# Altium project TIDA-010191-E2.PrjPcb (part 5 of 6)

## Sheet TIDA-010191-E2_Power-Supply_2.SchDoc
size 558 x 431 mm; Date: Not shown in title block; ApprovedBy: Not shown in title block; CheckedBy: Not shown in title block; Author: Not shown in title block; CompanyName: Not shown in title block; Engineer: Not shown in title block; Organization: Not shown in title block; Address1: Not shown in title block; Address2: Not shown in title block; Address3: Not shown in title block; Address4: Not shown in title block; DocumentNumber: 7; Revision: Use project parameter SCH_Rev; SheetNumber: 7; SheetTotal: 9; PageSetup: Record=PageOptions¦CenterHorizontal=True¦CenterVertical=True¦PrintScale=1.00¦XCorrection=1.00¦YCorrection=1.00¦PrintKind=0¦BorderSize=5000000¦LeftOffset=0¦BottomOffset=0¦Orientation=2¦PaperLength=1000¦PaperWidth=1000¦Scale=100¦PaperSource=15¦PrintQuality=600¦MediaType=1¦DitherType=10¦PaperKind=Letter¦PrintScaleMode=1
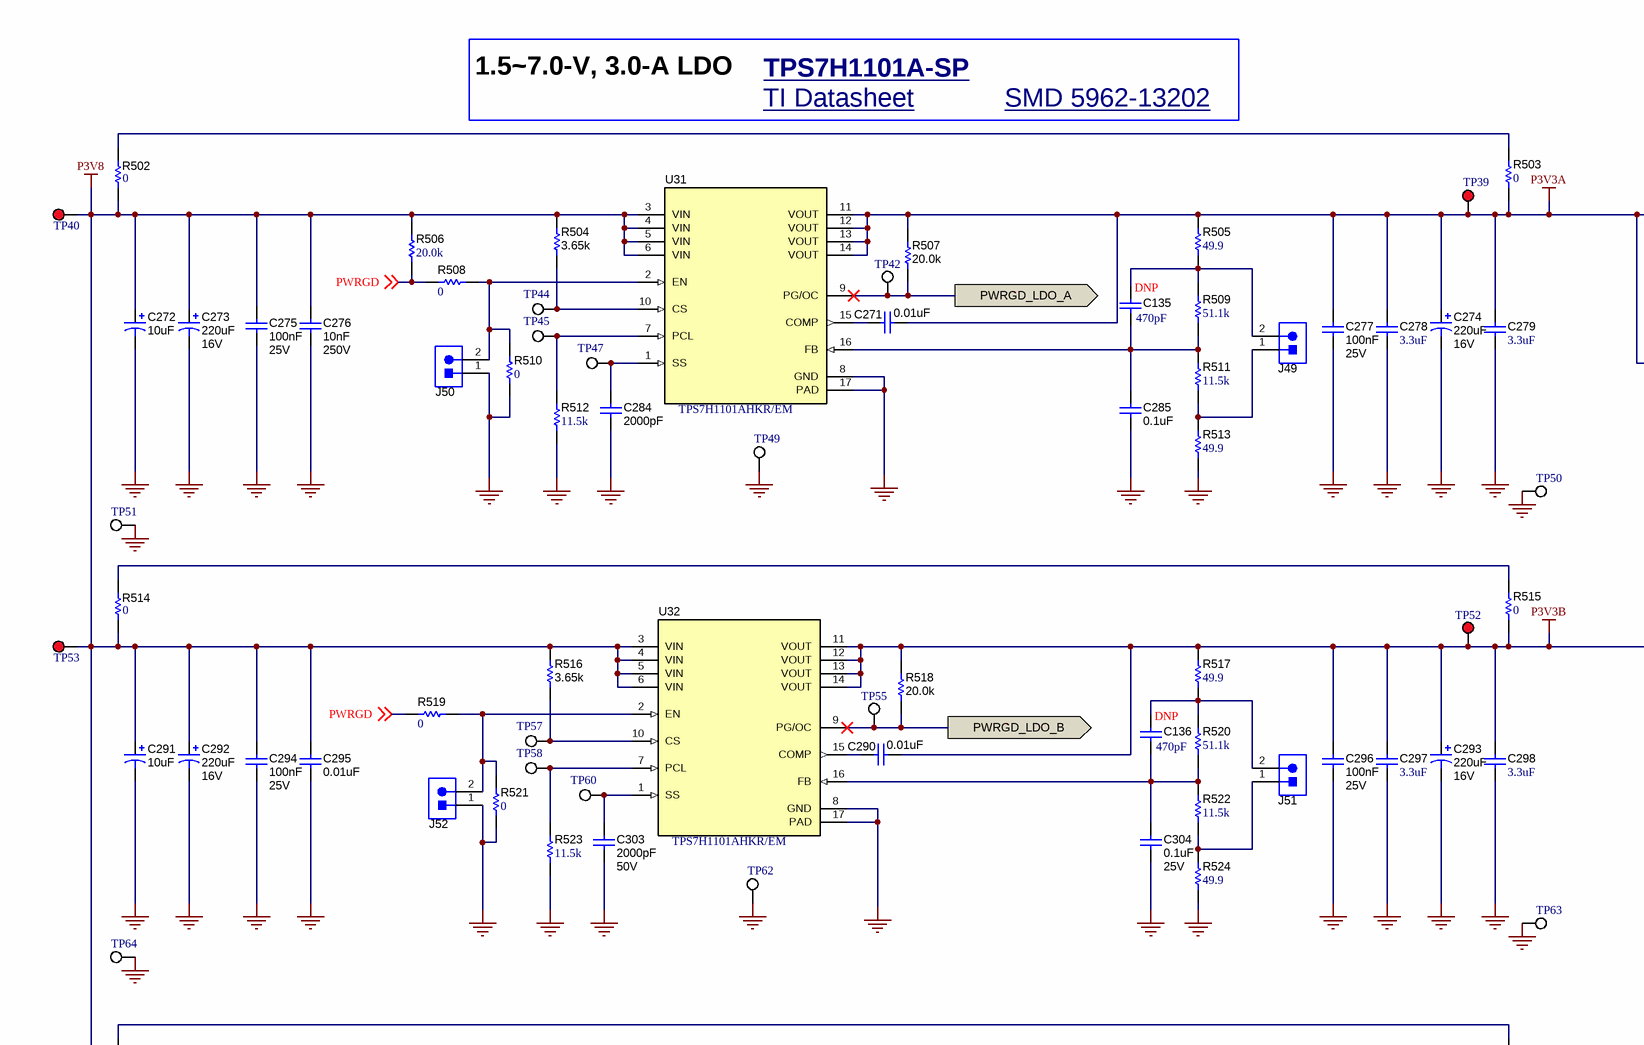
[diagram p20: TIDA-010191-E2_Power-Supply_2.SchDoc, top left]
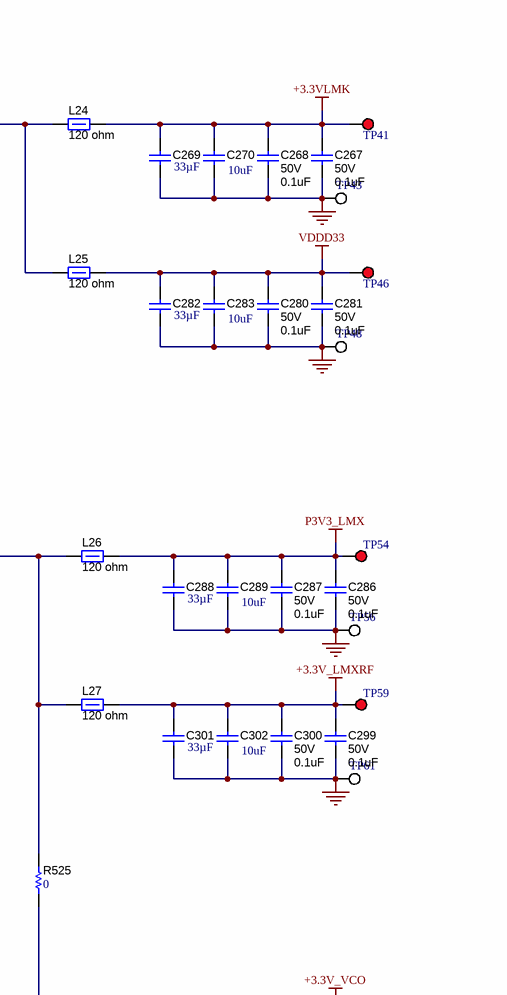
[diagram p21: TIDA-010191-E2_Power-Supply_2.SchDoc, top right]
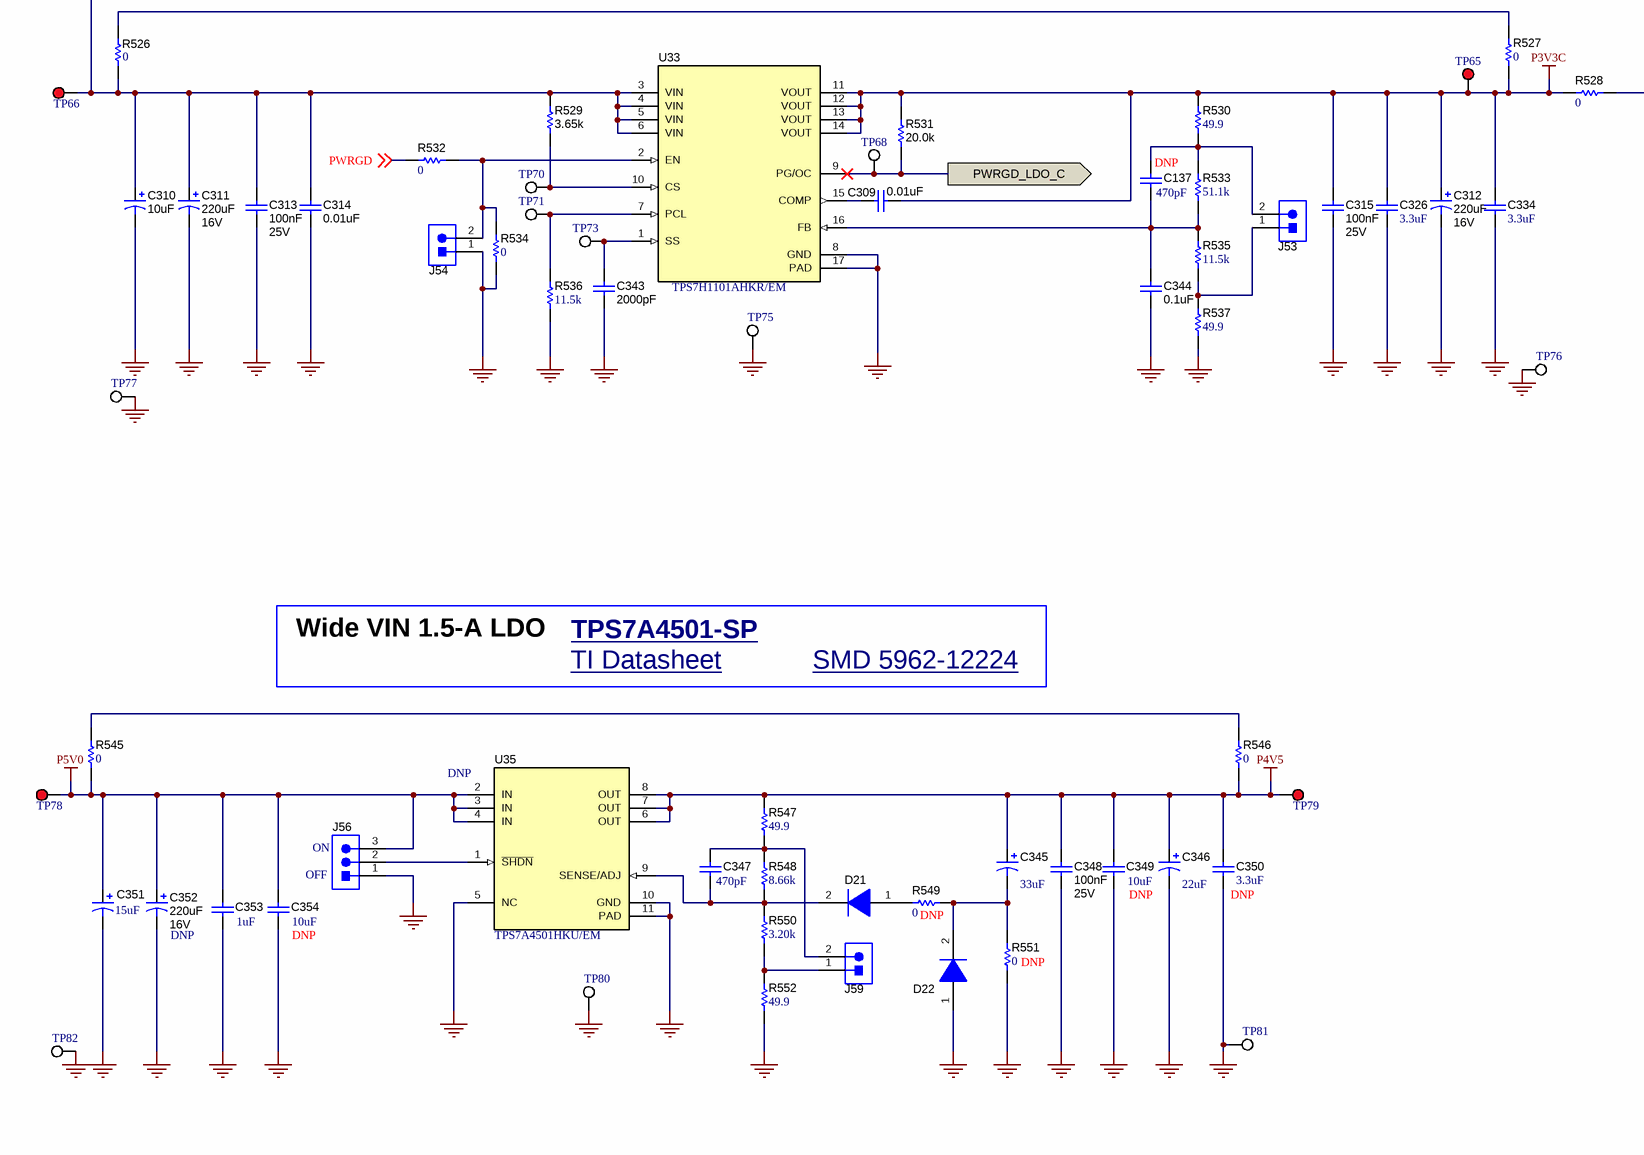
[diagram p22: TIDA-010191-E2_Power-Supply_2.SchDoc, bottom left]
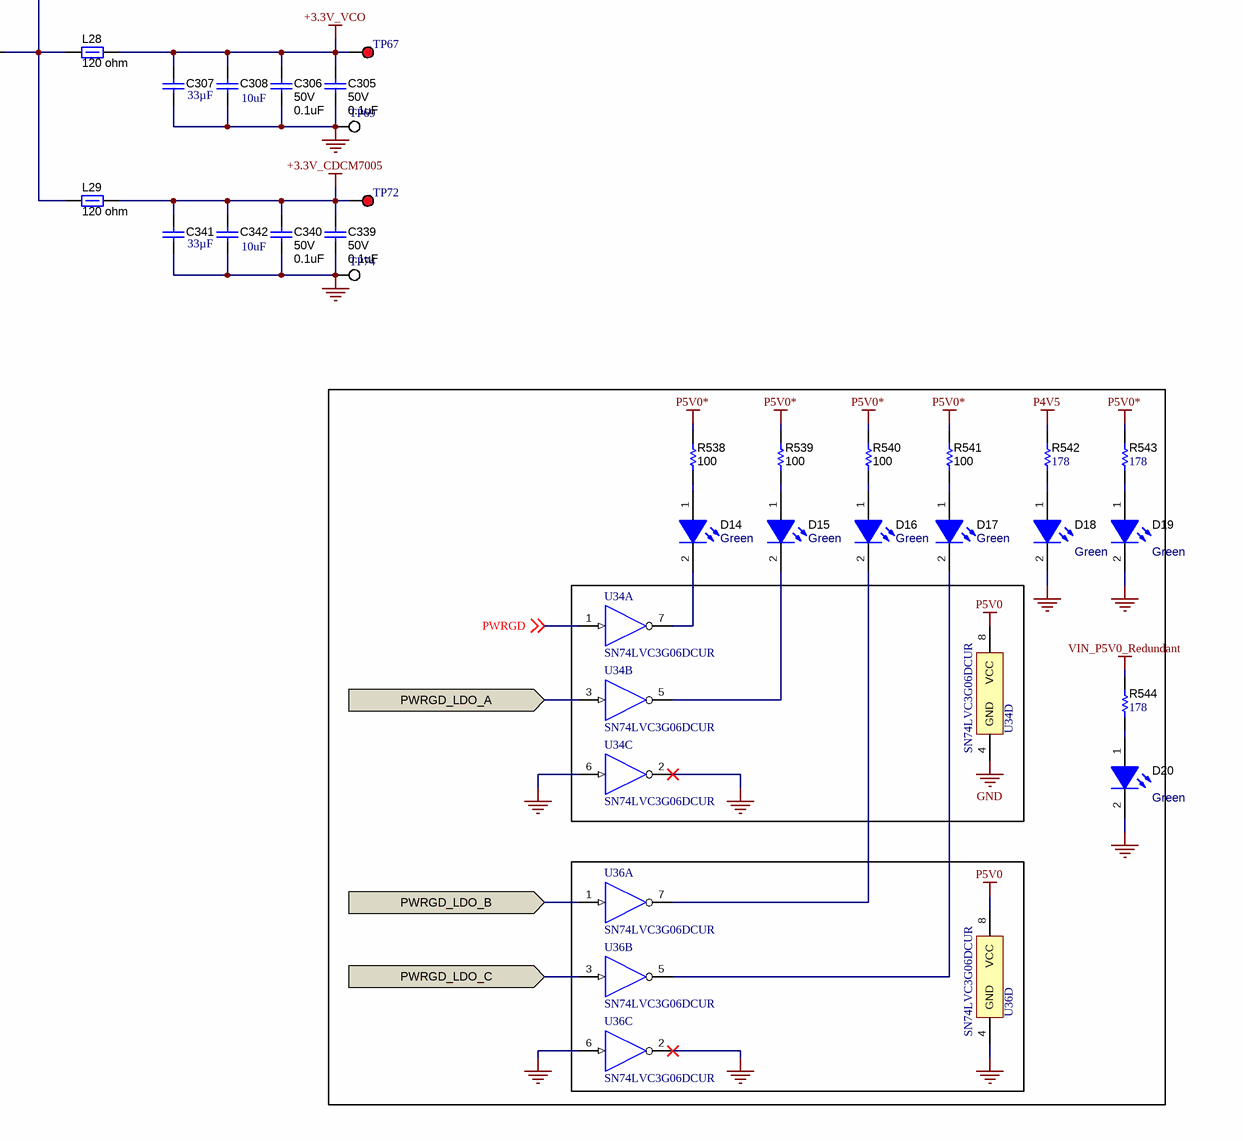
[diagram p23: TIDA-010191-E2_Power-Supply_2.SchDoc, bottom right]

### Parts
C135  ValueDisplayed: 470pF  [0805_HV]  (hidden comment: CGJ4C2C0G1H471J060AA)
C136  ValueDisplayed: 470pF  [0805_HV]  (hidden comment: CGJ4C2C0G1H471J060AA)
C137  ValueDisplayed: 470pF  [0805_HV]  (hidden comment: CGJ4C2C0G1H471J060AA)
C267  VDC_V: 50V  ValueDisplayed: 0.1uF  [1206]  (hidden comment: 12065C104JAT2A)
C268  VDC_V: 50V  ValueDisplayed: 0.1uF  [1206]  (hidden comment: 12065C104JAT2A)
C269  ValueDisplayed: 33µF  [2220_310]  (hidden comment: KTS250B336M55N0T00)
C270  ValueDisplayed: 10uF  [2220_280]  (hidden comment: 22201C106MAT2A)
C271  ValueDisplayed: 0.01uF  [0805_HV]  (hidden comment: Capacitor)
C272  ValueDisplayed: 10uF  [7343-43]  (hidden comment: Cap_Polarized)
C273  ValueDisplayed: 220uF  VDC_V: 16V  [7343-43]  (hidden comment: CMP-0011955-2)
C274  ValueDisplayed: 220uF  VDC_V: 16V  [7343-43]  (hidden comment: CMP-0011955-2)
C275  Cap_F: 100nF  VDC_V: 25V  [0805_HV]  (hidden comment: C0805C104K3RACTU)
C276  Cap_F: 10nF  VDC_V: 250V  [0805_HV]  (hidden comment: CMP-0008376-2)
C277  Cap_F: 100nF  VDC_V: 25V  [0805_HV]  (hidden comment: C0805C104K3RACTU)
C278  ValueDisplayed: 3.3uF  [1812_220]  (hidden comment: CGA8M2X7R1H335K200KA)
C279  ValueDisplayed: 3.3uF  [1812_220]  (hidden comment: CGA8M2X7R1H335K200KA)
C280  VDC_V: 50V  ValueDisplayed: 0.1uF  [1206]  (hidden comment: 12065C104JAT2A)
C281  VDC_V: 50V  ValueDisplayed: 0.1uF  [1206]  (hidden comment: 12065C104JAT2A)
C282  ValueDisplayed: 33µF  [2220_310]  (hidden comment: KTS250B336M55N0T00)
C283  ValueDisplayed: 10uF  [2220_280]  (hidden comment: 22201C106MAT2A)
C284  ValueDisplayed: 2000pF  [0805_HV]  (hidden comment: Capacitor)
C285  ValueDisplayed: 0.1uF  [1206_180]  (hidden comment: Capacitor)
C286  VDC_V: 50V  ValueDisplayed: 0.1uF  [1206]  (hidden comment: 12065C104JAT2A)
C287  VDC_V: 50V  ValueDisplayed: 0.1uF  [1206]  (hidden comment: 12065C104JAT2A)
C288  ValueDisplayed: 33µF  [2220_310]  (hidden comment: KTS250B336M55N0T00)
C289  ValueDisplayed: 10uF  [2220_280]  (hidden comment: 22201C106MAT2A)
C290  ValueDisplayed: 0.01uF  [0805_HV]  (hidden comment: Capacitor)
C291  ValueDisplayed: 10uF  [7343-43]  (hidden comment: Cap_Polarized)
C292  ValueDisplayed: 220uF  VDC_V: 16V  [7343-43]  (hidden comment: CMP-0011955-2)
C293  ValueDisplayed: 220uF  VDC_V: 16V  [7343-43]  (hidden comment: CMP-0011955-2)
C294  Cap_F: 100nF  VDC_V: 25V  [0805_HV]  (hidden comment: C0805C104K3RACTU)
C295  ValueDisplayed: 0.01uF  [0805_HV]  (hidden comment: Capacitor)
C296  Cap_F: 100nF  VDC_V: 25V  [0805_HV]  (hidden comment: C0805C104K3RACTU)
C297  ValueDisplayed: 3.3uF  [1812_220]  (hidden comment: CGA8M2X7R1H335K200KA)
C298  ValueDisplayed: 3.3uF  [1812_220]  (hidden comment: CGA8M2X7R1H335K200KA)
C299  VDC_V: 50V  ValueDisplayed: 0.1uF  [1206]  (hidden comment: 12065C104JAT2A)
C300  VDC_V: 50V  ValueDisplayed: 0.1uF  [1206]  (hidden comment: 12065C104JAT2A)
C301  ValueDisplayed: 33µF  [2220_310]  (hidden comment: KTS250B336M55N0T00)
C302  ValueDisplayed: 10uF  [2220_280]  (hidden comment: 22201C106MAT2A)
C303  ValueDisplayed: 2000pF  VDC_V: 50V  [0805_HV]  (hidden comment: CMP-0008070-2)
C304  ValueDisplayed: 0.1uF  VDC_V: 25V  [1206_180]  (hidden comment: CMP-0064950-2)
C305  VDC_V: 50V  ValueDisplayed: 0.1uF  [1206]  (hidden comment: 12065C104JAT2A)
C306  VDC_V: 50V  ValueDisplayed: 0.1uF  [1206]  (hidden comment: 12065C104JAT2A)
C307  ValueDisplayed: 33µF  [2220_310]  (hidden comment: KTS250B336M55N0T00)
C308  ValueDisplayed: 10uF  [2220_280]  (hidden comment: 22201C106MAT2A)
C309  ValueDisplayed: 0.01uF  [0805_HV]  (hidden comment: Capacitor)
C310  ValueDisplayed: 10uF  [7343-43]  (hidden comment: Cap_Polarized)
C311  ValueDisplayed: 220uF  VDC_V: 16V  [7343-43]  (hidden comment: CMP-0011955-2)
C312  ValueDisplayed: 220uF  VDC_V: 16V  [7343-43]  (hidden comment: CMP-0011955-2)
C313  Cap_F: 100nF  VDC_V: 25V  [0805_HV]  (hidden comment: C0805C104K3RACTU)
C314  ValueDisplayed: 0.01uF  [0805_HV]  (hidden comment: Capacitor)
C315  Cap_F: 100nF  VDC_V: 25V  [0805_HV]  (hidden comment: C0805C104K3RACTU)
C326  ValueDisplayed: 3.3uF  [1812_220]  (hidden comment: CGA8M2X7R1H335K200KA)
C334  ValueDisplayed: 3.3uF  [1812_220]  (hidden comment: CGA8M2X7R1H335K200KA)
C339  VDC_V: 50V  ValueDisplayed: 0.1uF  [1206]  (hidden comment: 12065C104JAT2A)
C340  VDC_V: 50V  ValueDisplayed: 0.1uF  [1206]  (hidden comment: 12065C104JAT2A)
C341  ValueDisplayed: 33µF  [2220_310]  (hidden comment: KTS250B336M55N0T00)
C342  ValueDisplayed: 10uF  [2220_280]  (hidden comment: 22201C106MAT2A)
C343  ValueDisplayed: 2000pF  [0805_HV]  (hidden comment: Capacitor)
C344  ValueDisplayed: 0.1uF  [1206_180]  (hidden comment: Capacitor)
C345  ValueDisplayed: 33uF  [6032-28]  (hidden comment: TPSC336K010R0375)
C346  ValueDisplayed: 22uF  [7343-31]  (hidden comment: TPSD226K025R0100)
C347  ValueDisplayed: 470pF  [0805_HV]  (hidden comment: CGJ4C2C0G1H471J060AA)
C348  Cap_F: 100nF  VDC_V: 25V  [0805_HV]  (hidden comment: C0805C104K3RACTU)
C349  ValueDisplayed: 10uF  [2220_280]  (hidden comment: 22201C106MAT2A)
C350  ValueDisplayed: 3.3uF  [1812_220]  (hidden comment: CGA8M2X7R1H335K200KA)
C351  ValueDisplayed: 15uF  [7343-31]  (hidden comment: TPSD156K035R0300)
C352  ValueDisplayed: 220uF  VDC_V: 16V  [7343-43]  (hidden comment: CMP-0011955-2)
C353  ValueDisplayed: 1uF  [1812_254]  (hidden comment: C4532X7R2A105K230KA)
C354  ValueDisplayed: 10uF  [2220_280]  (hidden comment: 22201C106MAT2A)
D14  value Green  [LTST-C191_Green]  (hidden comment: LTST-C191KGKT)
D15  value Green  [LTST-C191_Green]  (hidden comment: LTST-C191KGKT)
D16  value Green  [LTST-C191_Green]  (hidden comment: LTST-C191KGKT)
D17  value Green  [LTST-C191_Green]  (hidden comment: LTST-C191KGKT)
D18  value Green  [LTST-C191_Green]  (hidden comment: LTST-C191KGKT)
D19  value Green  [LTST-C191_Green]  (hidden comment: LTST-C191KGKT)
D20  value Green  [LTST-C191_Green]  (hidden comment: LTST-C191KGKT)
D21  1N6642UD1  [ST_LCC-2D]  (value not drawn)
D22  1N6642UD1  [ST_LCC-2D]  (value not drawn)
J49  HTSW-102-07-G-S  [Samtec_HTSW-102-07-G-S]  (value not drawn)
J50  HTSW-102-07-G-S  [Samtec_HTSW-102-07-G-S]  (value not drawn)
J51  HTSW-102-07-G-S  [Samtec_HTSW-102-07-G-S]  (value not drawn)
J52  HTSW-102-07-G-S  [Samtec_HTSW-102-07-G-S]  (value not drawn)
J53  HTSW-102-07-G-S  [Samtec_HTSW-102-07-G-S]  (value not drawn)
J54  HTSW-102-07-G-S  [Samtec_HTSW-102-07-G-S]  (value not drawn)
J56  HTSW-103-07-G-S  [Samtec_HTSW-103-07-G-S]  (value not drawn)
J59  HTSW-102-07-G-S  [Samtec_HTSW-102-07-G-S]  (value not drawn)
L24  ValueDisplayed: 120 ohm  [1206]  (hidden comment: Ferrite_Bead)
L25  ValueDisplayed: 120 ohm  [1206]  (hidden comment: Ferrite_Bead)
L26  ValueDisplayed: 120 ohm  [1206]  (hidden comment: Ferrite_Bead)
L27  ValueDisplayed: 120 ohm  [1206]  (hidden comment: Ferrite_Bead)
L28  ValueDisplayed: 120 ohm  [1206]  (hidden comment: Ferrite_Bead)
L29  ValueDisplayed: 120 ohm  [1206]  (hidden comment: Ferrite_Bead)
R502  ValueDisplayed: 0  [2512]  (hidden comment: RMC1JPTE)
R503  ValueDisplayed: 0  [2512]  (hidden comment: RMC1JPTE)
R504  ValueDisplayed: 3.65k  [1206]  (hidden comment: ERJ-8ENF3651V)
R505  ValueDisplayed: 49.9  [0805_HV]  (hidden comment: M55342K06B49D9T)
R506  ValueDisplayed: 20.0k  [0805_HV]  (hidden comment: CRCW080520K0FKEA)
R507  ValueDisplayed: 20.0k  [0805_HV]  (hidden comment: Resistor)
R508  ValueDisplayed: 0  [0805_HV]  (hidden comment: PMR10EZPJ000)
R509  ValueDisplayed: 51.1k  [0805_HV]  (hidden comment: RT0805BRD0751K1L)
R510  ValueDisplayed: 0  [0805_HV]  (hidden comment: PMR10EZPJ000)
R511  ValueDisplayed: 11.5k  [0805_HV]  (hidden comment: RT0805BRD0711K5L)
R512  ValueDisplayed: 11.5k  [0805_HV]  (hidden comment: RT0805BRD0711K5L)
R513  ValueDisplayed: 49.9  [0805_HV]  (hidden comment: M55342K06B49D9T)
R514  ValueDisplayed: 0  [2512]  (hidden comment: RMC1JPTE)
R515  ValueDisplayed: 0  [2512]  (hidden comment: RMC1JPTE)
R516  ValueDisplayed: 3.65k  [1206]  (hidden comment: ERJ-8ENF3651V)
R517  ValueDisplayed: 49.9  [0805_HV]  (hidden comment: M55342K06B49D9T)
R518  ValueDisplayed: 20.0k  [0805_HV]  (hidden comment: CMP-0021614-3)
R519  ValueDisplayed: 0  [0805_HV]  (hidden comment: PMR10EZPJ000)
R520  ValueDisplayed: 51.1k  [0805_HV]  (hidden comment: RT0805BRD0751K1L)
R521  ValueDisplayed: 0  [0805_HV]  (hidden comment: PMR10EZPJ000)
R522  ValueDisplayed: 11.5k  [0805_HV]  (hidden comment: RT0805BRD0711K5L)
R523  ValueDisplayed: 11.5k  [0805_HV]  (hidden comment: RT0805BRD0711K5L)
R524  ValueDisplayed: 49.9  [0805_HV]  (hidden comment: M55342K06B49D9T)
R525  ValueDisplayed: 0  [2512]  (hidden comment: RMC1JPTE)
R526  ValueDisplayed: 0  [2512]  (hidden comment: RMC1JPTE)
R527  ValueDisplayed: 0  [2512]  (hidden comment: RMC1JPTE)
R528  ValueDisplayed: 0  [2512]  (hidden comment: RMC1JPTE)
R529  ValueDisplayed: 3.65k  [1206]  (hidden comment: ERJ-8ENF3651V)
R530  ValueDisplayed: 49.9  [0805_HV]  (hidden comment: M55342K06B49D9T)
R531  ValueDisplayed: 20.0k  [0805_HV]  (hidden comment: CMP-0021614-3)
R532  ValueDisplayed: 0  [0805_HV]  (hidden comment: PMR10EZPJ000)
R533  ValueDisplayed: 51.1k  [0805_HV]  (hidden comment: RT0805BRD0751K1L)
R534  ValueDisplayed: 0  [0805_HV]  (hidden comment: PMR10EZPJ000)
R535  ValueDisplayed: 11.5k  [0805_HV]  (hidden comment: RT0805BRD0711K5L)
R536  ValueDisplayed: 11.5k  [0805_HV]  (hidden comment: RT0805BRD0711K5L)
R537  ValueDisplayed: 49.9  [0805_HV]  (hidden comment: M55342K06B49D9T)
R538  ValueDisplayed: 100  [0603]  (hidden comment: CMP-0021991-4)
R539  ValueDisplayed: 100  [0603]  (hidden comment: CMP-0021991-4)
R540  ValueDisplayed: 100  [0603]  (hidden comment: CMP-0021991-4)
R541  ValueDisplayed: 100  [0603]  (hidden comment: CMP-0021991-4)
R542  ValueDisplayed: 178  [0603]  (hidden comment: RC0603FR-07178RL)
R543  ValueDisplayed: 178  [0603]  (hidden comment: RC0603FR-07178RL)
R544  ValueDisplayed: 178  [0603]  (hidden comment: RC0603FR-07178RL)
R545  ValueDisplayed: 0  [2512]  (hidden comment: RMC1JPTE)
R546  ValueDisplayed: 0  [2512]  (hidden comment: RMC1JPTE)
R547  ValueDisplayed: 49.9  [0805_HV]  (hidden comment: RT0805BRD0749R9L)
R548  ValueDisplayed: 8.66k  [0805_HV]  (hidden comment: RT0805BRD078K66L)
R549  ValueDisplayed: 0  [0805_HV]  (hidden comment: PMR10EZPJ000)
R550  ValueDisplayed: 3.20k  [0805_HV]  (hidden comment: RT0805BRD073K2L)
R551  ValueDisplayed: 0  [0805_HV]  (hidden comment: PMR10EZPJ000)
R552  ValueDisplayed: 49.9  [0805_HV]  (hidden comment: RT0805BRD0749R9L)
TP39  5000  [Keystone5000]  (value not drawn)
TP40  5000  [Keystone5000]  (value not drawn)
TP41  5000  [Keystone5000]  (value not drawn)
TP42  5002  [Keystone5002]  (value not drawn)
TP43  5015  [Testpoint_Keystone_Miniature]  (value not drawn)
TP44  5002  [Keystone5002]  (value not drawn)
TP45  5002  [Keystone5002]  (value not drawn)
TP46  5000  [Keystone5000]  (value not drawn)
TP47  5002  [Keystone5002]  (value not drawn)
TP48  5015  [Testpoint_Keystone_Miniature]  (value not drawn)
TP49  5015  [Testpoint_Keystone_Miniature]  (value not drawn)
TP50  5015  [Testpoint_Keystone_Miniature]  (value not drawn)
TP51  5015  [Testpoint_Keystone_Miniature]  (value not drawn)
TP52  5000  [Keystone5000]  (value not drawn)
TP53  5000  [Keystone5000]  (value not drawn)
TP54  5000  [Keystone5000]  (value not drawn)
TP55  5002  [Keystone5002]  (value not drawn)
TP56  5015  [Testpoint_Keystone_Miniature]  (value not drawn)
TP57  5002  [Keystone5002]  (value not drawn)
TP58  5002  [Keystone5002]  (value not drawn)
TP59  5000  [Keystone5000]  (value not drawn)
TP60  5002  [Keystone5002]  (value not drawn)
TP61  5015  [Testpoint_Keystone_Miniature]  (value not drawn)
TP62  5015  [Testpoint_Keystone_Miniature]  (value not drawn)
TP63  5015  [Testpoint_Keystone_Miniature]  (value not drawn)
TP64  5015  [Testpoint_Keystone_Miniature]  (value not drawn)
TP65  5000  [Keystone5000]  (value not drawn)
TP66  5000  [Keystone5000]  (value not drawn)
TP67  5000  [Keystone5000]  (value not drawn)
TP68  5002  [Keystone5002]  (value not drawn)
TP69  5015  [Testpoint_Keystone_Miniature]  (value not drawn)
TP70  5002  [Keystone5002]  (value not drawn)
TP71  5002  [Keystone5002]  (value not drawn)
TP72  5000  [Keystone5000]  (value not drawn)
TP73  5002  [Keystone5002]  (value not drawn)
TP74  5015  [Testpoint_Keystone_Miniature]  (value not drawn)
TP75  5015  [Testpoint_Keystone_Miniature]  (value not drawn)
TP76  5015  [Testpoint_Keystone_Miniature]  (value not drawn)
TP77  5015  [Testpoint_Keystone_Miniature]  (value not drawn)
TP78  5000  [Keystone5000]  (value not drawn)
TP79  5000  [Keystone5000]  (value not drawn)
TP80  5015  [Testpoint_Keystone_Miniature]  (value not drawn)
TP81  5015  [Testpoint_Keystone_Miniature]  (value not drawn)
TP82  5015  [Testpoint_Keystone_Miniature]  (value not drawn)
U31  TPS7H1101AHKR/EM  [HKR0016A_Custom_A]
U32  TPS7H1101AHKR/EM  [HKR0016A_Custom_A]
U33  TPS7H1101AHKR/EM  [HKR0016A_Custom_A]
U34  SN74LVC3G06DCUR  [DCU0008A_N]  (parts A,B,C,D of 4)
U35  TPS7A4501HKU/EM  [HKU0010_CUSTOM_A]
U36  SN74LVC3G06DCUR  [DCU0008A_N]  (parts A,B,C,D of 4)

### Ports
PWRGD_LDO_A (in), PWRGD_LDO_A (out), PWRGD_LDO_B (in), PWRGD_LDO_B (out), PWRGD_LDO_C (in), PWRGD_LDO_C (out)

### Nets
+3.3V_CDCM7005: C339.2 C340.2 C341.1 C342.1 L29.2 TP72.1
+3.3V_LMXRF: C299.2 C300.2 C301.1 C302.1 L27.2 TP59.1
+3.3V_VCO: C305.2 C306.2 C307.1 C308.1 L28.2 TP67.1
+3.3VLMK: C267.2 C268.2 C269.1 C270.1 L24.2 TP41.1
GND: C267.1 C268.1 C269.2 C270.2 C272.2(-) C273.2(-) C274.2(-) C275.2 C276.2 C277.2 C278.2 C279.2 C280.1 C281.1 C282.2 C283.2 C284.2 C285.2 C286.1 C287.1 C288.2 C289.2 C291.2(-) C292.2(-) C293.2(-) C294.2 C295.2 C296.2 C297.2 C298.2 C299.1 C300.1 C301.2 C302.2 C303.2 C304.2 C305.1 C306.1 C307.2 C308.2 C310.2(-) C311.2(-) C312.2(-) C313.2 C314.2 C315.2 C326.2 C334.2 C339.1 C340.1 C341.2 C342.2 C343.2 C344.2 C346.2(-) C348.2 C349.2 C350.2 C351.2(-) C352.2(-) C353.2 C354.2 D18.2(K) D19.2(K) D20.2(K) D22.1(A) J50.1 J52.1 J54.1 J56.1 R510.1 R512.1 R513.1 R521.1 R523.1 R524.1 R534.1 R536.1 R537.1 R551.1 R552.1 TP43.1 TP48.1 TP49.1 TP50.1 TP51.1 TP56.1 TP61.1 TP62.1 TP63.1 TP64.1 TP69.1 TP74.1 TP75.1 TP76.1 TP77.1 TP80.1 TP81.1 TP82.1 U31.8(GND) U31.17(PAD) U32.8(GND) U32.17(PAD) U33.8(GND) U33.17(PAD) U34.2(3Y) U34.4(GND) U34.6(3A) U35.5(NC) U35.10(GND) U35.11(PAD) U36.2(3Y) U36.4(GND) U36.6(3A)
P3V3_LMX: C286.2 C287.2 C288.1 C289.1 L26.2 TP54.1
P3V3A: C271.2 C274.1(+) C277.1 C278.1 C279.1 L24.1 L25.1 R503.2 R505.2 R507.1 TP39.1 U31.11(VOUT) U31.12(VOUT) U31.13(VOUT) U31.14(VOUT)
P3V3B: C290.2 C293.1(+) C296.1 C297.1 C298.1 L26.1 L27.1 R515.2 R517.2 R518.1 R525.2 TP52.1 U32.11(VOUT) U32.12(VOUT) U32.13(VOUT) U32.14(VOUT)
P3V3C: C309.2 C312.1(+) C315.1 C326.1 C334.1 R527.2 R528.1 R530.2 R531.1 TP65.1 U33.11(VOUT) U33.12(VOUT) U33.13(VOUT) U33.14(VOUT)
P3V8: C272.1(+) C273.1(+) C275.1 C276.1 C291.1(+) C292.1(+) C294.1 C295.1 C310.1(+) C311.1(+) C313.1 C314.1 R502.2 R504.2 R506.2 R514.2 R516.2 R526.2 R529.2 TP40.1 TP53.1 TP66.1 U31.3(VIN) U31.4(VIN) U31.5(VIN) U31.6(VIN) U32.3(VIN) U32.4(VIN) U32.5(VIN) U32.6(VIN) U33.3(VIN) U33.4(VIN) U33.5(VIN) U33.6(VIN)
P4V5: C345.1(+) C346.1(+) C348.1 C349.1 C350.1 R542.2 R546.2 R547.2 TP79.1 U35.6(OUT) U35.7(OUT) U35.8(OUT)
P5V0: C351.1(+) C352.1(+) C353.1 C354.1 J56.3 R545.2 TP78.1 U34.8(VCC) U35.2(IN) U35.3(IN) U35.4(IN) U36.8(VCC)
P5V0*: R538.1 R539.1 R540.1 R541.1 R543.2
VDDD33: C280.2 C281.2 C282.1 C283.1 L25.2 TP46.1
VIN_P5V0_Redundant: R544.2
PWRGD: R506.1 R508.1 R519.1 R532.1 U34.1(1A) ; off-sheet PWRGD
PWRGD_LDO_A: R507.2 TP42.1 U31.9(PG/OC) U34.3(2A) ; port PWRGD_LDO_A
PWRGD_LDO_B: R518.2 TP55.1 U32.9(PG/OC) U36.1(1A) ; port PWRGD_LDO_B
PWRGD_LDO_C: R531.2 TP68.1 U33.9(PG/OC) U36.3(2A) ; port PWRGD_LDO_C
NetC135_1: C135.1 J49.2 R505.1 R509.2
NetC135_2: C135.2 C285.1 R509.1 R511.2 U31.16(FB)
NetC136_1: C136.1 J51.2 R517.1 R520.2
NetC136_2: C136.2 C304.1 R520.1 R522.2 U32.16(FB)
NetC137_1: C137.1 J53.2 R530.1 R533.2
NetC137_2: C137.2 C344.1 R533.1 R535.2 U33.16(FB)
NetC271_1: C271.1 U31.15(COMP)
NetC284_1: C284.1 TP47.1 U31.1(SS)
NetC290_1: C290.1 U32.15(COMP)
NetC303_1: C303.1 TP60.1 U32.1(SS)
NetC309_1: C309.1 U33.15(COMP)
NetC343_1: C343.1 TP73.1 U33.1(SS)
NetC345_2: C345.2(-) D22.2(K) R549.2 R551.2
NetC347_1: C347.1 J59.2 R547.1 R548.2
NetC347_2: C347.2 D21.2(K) R548.1 R550.2 U35.9(SENSE/ADJ)
NetD14_1: D14.1(A) R538.2
NetD14_2: D14.2(K) U34.7(1Y)
NetD15_1: D15.1(A) R539.2
NetD15_2: D15.2(K) U34.5(2Y)
NetD16_1: D16.1(A) R540.2
NetD16_2: D16.2(K) U36.7(1Y)
NetD17_1: D17.1(A) R541.2
NetD17_2: D17.2(K) U36.5(2Y)
NetD18_1: D18.1(A) R542.1
NetD19_1: D19.1(A) R543.1
NetD20_1: D20.1(A) R544.1
NetD21_1: D21.1(A) R549.1
NetJ49_1: J49.1 R511.1 R513.2
NetJ50_2: J50.2 R508.2 R510.2 U31.2(EN)
NetJ51_1: J51.1 R522.1 R524.2
NetJ52_2: J52.2 R519.2 R521.2 U32.2(EN)
NetJ53_1: J53.1 R535.1 R537.2
NetJ54_2: J54.2 R532.2 R534.2 U33.2(EN)
NetJ56_2: J56.2 U35.1(~{SHDN})
NetJ59_1: J59.1 R550.1 R552.2
NetL28_1: L28.1 L29.1 R525.1 R528.2
NetR502_1: R502.1 R503.1
NetR504_1: R504.1 TP44.1 U31.10(CS)
NetR512_2: R512.2 TP45.1 U31.7(PCL)
NetR514_1: R514.1 R515.1
NetR516_1: R516.1 TP57.1 U32.10(CS)
NetR523_2: R523.2 TP58.1 U32.7(PCL)
NetR526_1: R526.1 R527.1
NetR529_1: R529.1 TP70.1 U33.10(CS)
NetR536_2: R536.2 TP71.1 U33.7(PCL)
NetR545_1: R545.1 R546.1

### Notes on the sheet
- 1.5~7.0-V, 3.0-A LDO
- TI Datasheet <http://www.ti.com/lit/gpn/TPS7H1101A-SP>
- TPS7H1101A-SP <http://www.ti.com/product/TPS7H1101A-SP>
- SMD 5962-13202 <https://landandmaritimeapps.dla.mil/Downloads/MilSpec/Smd/13202.pdf>
- (near C135) DNP
- (near C136) DNP
- (near C137) DNP
- Wide VIN 1.5-A LDO
- TPS7A4501-SP <http://www.ti.com/product/TPS7A4501-SP>
- TI Datasheet <http://www.ti.com/lit/gpn/TPS7A4501-SP>
- SMD 5962-12224 <https://landandmaritimeapps.dla.mil/Downloads/MilSpec/Smd/12224.pdf>
- (near U35) DNP
- OFF
- (near J56) ON
- DNP
- (near C350) DNP
- (near C352) DNP
- (near C354) DNP
- (near R549) DNP
- (near R551) DNP

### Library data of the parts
C135-C137 C347 = CMP-0007985-2: CAP, CERM, 470 pF, 50 V, +/- 5%, C0G/NP0, 0805; Manufacturer: TDK; TaMin_C: -55°C; Polarized: N; SizeAreaWB_mm2: 6.75; Value1: Unknown; U/M: EA; Value: 470pF; TaMax_C: 125°C; SizeZ_mm: 1.45; SizeX_mm: 2; SizeY_mm: 1.25; Cap_Case: 0805; Value2: 50V; SizeArea_mm2: 2.5; AEC Category: Q200
C267 C268 C280 C281 C286 C287 C299 C300 C305 C306 C339 C340 = CMP-0008532-2: CAP, CERM, 0.1 uF, 50 V, +/- 5%, X7R, 1206; Manufacturer: AVX; TaMin_C: -55°C; ESR_ohm: 0.037; Polarized: N; SizeAreaWB_mm2: 10.92; Value1: 0.037 ohm; U/M: EA; Value: 0.1uF; TaMax_C: 125°C; SizeZ_mm: 1.35; SizeX_mm: 3.2; SizeY_mm: 1.6; SizeArea_mm2: 5.12; Cap_F: 100nF; AEC Category: Q200
C269 C282 C288 C301 C307 C341 = CMP-0080078-1: CAP, CERM, 33 µF, 25 V,+/- 20%, X7R, 2220; Manufacturer: Chemi-Con; TaMin_C: -55°C; Polarized: N; SizeAreaWB_mm2: 53.9; U/M: EA; Value: 33uF; TaMax_C: 125°C; SizeZ_mm: 3.1; SizeX_mm: 5.7; SizeY_mm: 5; Cap_Case: 2220; Value2: 25V; SizeArea_mm2: 28.5; AEC Category: Q200
C270 C283 C289 C302 C308 C342 C349 C354 = CMP-0009304-2: CAP, CERM, 10 uF, 100 V, +/- 20%, X7R, 2220; Manufacturer: AVX; TaMin_C: -55°C; Polarized: N; SizeAreaWB_mm2: 53.9; Value1: Unknown; U/M: EA; Value: 10uF; TaMax_C: 125°C; SizeZ_mm: 2.8; SizeX_mm: 5.7; SizeY_mm: 5; Cap_Case: 2220; Value2: 100V; SizeArea_mm2: 28.5; Cap_F: 10µF; AEC Category: Q200
C271 C290 C295 C309 C314 = CMP-0008376-2: CAP, CERM, 0.01 uF, 250 V, +/- 10%, X7R, 0805; PartNumber: GRM21BR72E103KW03L; Manufacturer: MuRata; Polarized: N; Value: 0.01uF; U/M: EA; Cap_F: 10nF; Value1: Unknown; VDC_V: 250V; TaMin_C: -55°C; TaMax_C: 125°C; Cap_Case: 0805; SizeArea_mm2: 2.5; SizeAreaWB_mm2: 6.75; SizeX_mm: 2; SizeY_mm: 1.25; SizeZ_mm: 1.45; AEC Category: Q200
C272 C291 C310 = CMP-0011937-2: CAP, TA, 10 uF, 50 V, +/- 10%, 0.5 ohm, SMD; PartNumber: TPSE106K050R0500; Manufacturer: AVX; Polarized: Y; CompType: Capacitor; Value: 10uF; U/M: EA; Cap_F: 10µF; Value1: 0.5 ohm; VDC_V: 50V; ESR_ohm: 0.5; IRMS_A: 517mA; TaMin_C: -55°C; TaMax_C: 125°C; Cap_Case: E; SizeAreaWB_mm2: 58.59; SizeArea_mm2: 31.39; SizeX_mm: 7.3; SizeY_mm: 4.3; AEC Category: Q200
C273 C274 C292 C293 C311 C312 C352 = CMP-0011955-2: CAP, TA, 220 uF, 16 V, +/- 20%, 0.1 ohm, SMD; PartNumber: TPSE227M016R0100; Manufacturer: AVX; Polarized: Y; CompType: Capacitor; Value: 220uF; U/M: EA; Cap_F: 220µF; Value1: 0.1 ohm; ESR_ohm: 0.1; IRMS_A: 1.156A; TaMin_C: -55°C; TaMax_C: 125°C; Cap_Case: E; SizeAreaWB_mm2: 58.59; SizeArea_mm2: 31.39; SizeX_mm: 7.3; SizeY_mm: 4.3; AEC Category: Q200
C275 C277 C294 C296 C313 C315 C348 = CMP-0007723-2: CAP, CERM, 0.1 uF, 25 V, +/- 10%, X7R, 0805; Manufacturer: Kemet; TaMin_C: -55°C; ESR_ohm: 0.064; Polarized: N; SizeAreaWB_mm2: 6.75; Value1: 0.064 ohm; U/M: EA; Value: 0.1uF; TaMax_C: 125°C; SizeZ_mm: 1.45; SizeX_mm: 2; SizeY_mm: 1.25; Cap_Case: 0805; SizeArea_mm2: 2.5; IRMS_A: 1.64A; AEC Category: Q200
C276 = CMP-0008376-2: CAP, CERM, 0.01 uF, 250 V, +/- 10%, X7R, 0805; PartNumber: GRM21BR72E103KW03L; Manufacturer: MuRata; Polarized: N; Value: 0.01uF; U/M: EA; Value1: Unknown; TaMin_C: -55°C; TaMax_C: 125°C; Cap_Case: 0805; SizeArea_mm2: 2.5; SizeAreaWB_mm2: 6.75; SizeX_mm: 2; SizeY_mm: 1.25; SizeZ_mm: 1.45; AEC Category: Q200
C278 C279 C297 C298 C326 C334 C350 = CMP-0009392-2: CAP, CERM, 3.3 uF, 50 V, +/- 10%, X7R, AEC-Q200 Grade 1,; Manufacturer: TDK; TaMin_C: -55°C; ESR_ohm: 4.024m; Polarized: N; SizeAreaWB_mm2: 23.1; Value1: 0.004024 ohm; U/M: EA; Value: 3.3uF; TaMax_C: 125°C; SizeZ_mm: 2.2; SizeX_mm: 4.5; SizeY_mm: 3.2; Value2: 50V; SizeArea_mm2: 14.4; AEC Qualified: Y; Cap_F: 3.3µF; IRMS_A: 3.82481A; AEC Grade: 1; AEC Category: Q200
C284 C343 = CMP-0008070-2: CAP, CERM, 2000 pF, 50 V, +/- 5%, C0G/NP0, 0805; PartNumber: GRM2165C1H202JA01D; Manufacturer: MuRata; Polarized: N; Value: 2000pF; U/M: EA; Cap_F: 2nF; Value1: Unknown; VDC_V: 50V; TaMin_C: -55°C; TaMax_C: 125°C; Cap_Case: 0805; SizeArea_mm2: 2.5; SizeAreaWB_mm2: 6.75; SizeX_mm: 2; SizeY_mm: 1.25; SizeZ_mm: 1.45; AEC Category: Q200
C285 C344 = CMP-0064950-2: CAP, CERM, 0.1 uF, 25 V,+/- 5%, C0G/NP0, 1206; PartNumber: GRM31C5C1E104JA01L; Manufacturer: MuRata; Polarized: N; Value: 0.1uF; U/M: EA; Cap_F: 100nF; Value1: Unknown; VDC_V: 25V; TaMin_C: -55°C; TaMax_C: 125°C; Cap_Case: 1206; SizeArea_mm2: 5.12; SizeAreaWB_mm2: 10.92; SizeX_mm: 3.2; SizeY_mm: 1.6; SizeZ_mm: 1.8; AEC Category: Q200
C303 = CMP-0008070-2: CAP, CERM, 2000 pF, 50 V, +/- 5%, C0G/NP0, 0805; PartNumber: GRM2165C1H202JA01D; Manufacturer: MuRata; Polarized: N; Value: 2000pF; U/M: EA; Cap_F: 2nF; Value1: Unknown; TaMin_C: -55°C; TaMax_C: 125°C; Cap_Case: 0805; SizeArea_mm2: 2.5; SizeAreaWB_mm2: 6.75; SizeX_mm: 2; SizeY_mm: 1.25; SizeZ_mm: 1.45; AEC Category: Q200
C304 = CMP-0064950-2: CAP, CERM, 0.1 uF, 25 V,+/- 5%, C0G/NP0, 1206; PartNumber: GRM31C5C1E104JA01L; Manufacturer: MuRata; Polarized: N; Value: 0.1uF; U/M: EA; Cap_F: 100nF; Value1: Unknown; TaMin_C: -55°C; TaMax_C: 125°C; Cap_Case: 1206; SizeArea_mm2: 5.12; SizeAreaWB_mm2: 10.92; SizeX_mm: 3.2; SizeY_mm: 1.6; SizeZ_mm: 1.8; AEC Category: Q200
C345 = CMP-0011664-2: CAP, TA, 33 uF, 10 V, +/- 10%, 0.375 ohm, SMD; Manufacturer: AVX; TaMin_C: -55°C; ESR_ohm: 0.375; Polarized: Y; SizeAreaWB_mm2: 41.6; U/M: EA; Value: 33uF; TaMax_C: 125°C; SizeZ_mm: 2.8; SizeX_mm: 6; SizeY_mm: 3.2; Cap_Case: C; Value2: 10V; SizeArea_mm2: 19.2; CompType: Capacitor; Cap_F: 33µF; IRMS_A: 487mA; AEC Category: Q200
C346 = CMP-0011882-2: CAP, TA, 22 uF, 25 V, +/- 10%, 0.1 ohm, SMD; Manufacturer: AVX; TaMin_C: -55°C; ESR_ohm: 0.1; Polarized: Y; SizeAreaWB_mm2: 58.59; Value1: 0.1 ohm; U/M: EA; Value: 22uF; TaMax_C: 125°C; SizeZ_mm: 3.1; SizeX_mm: 7.3; SizeY_mm: 4.3; Cap_Case: D; Value2: 25V; SizeArea_mm2: 31.39; CompType: Capacitor; Cap_F: 22µF; IRMS_A: 1.102A; AEC Category: Q200
C351 = CMP-0011872-2: CAP, TA, 15 uF, 35 V, +/- 10%, 0.3 ohm, SMD; Manufacturer: AVX; TaMin_C: -55°C; ESR_ohm: 0.3; Polarized: Y; SizeAreaWB_mm2: 58.59; Value1: 0.3 ohm; U/M: EA; Value: 15uF; TaMax_C: 125°C; SizeZ_mm: 3.1; SizeX_mm: 7.3; SizeY_mm: 4.3; Cap_Case: D; Value2: 35V; SizeArea_mm2: 31.39; CompType: Capacitor; Cap_F: 15µF; IRMS_A: 636mA; AEC Category: Q200
C353 = CMP-0009354-2: CAP, CERM, 1 uF, 100 V, +/- 10%, X7R, 1812; Manufacturer: TDK; TaMin_C: -55°C; ESR_ohm: 5.865m; Polarized: N; SizeAreaWB_mm2: 23.1; Value1: 0.005865 ohm; U/M: EA; Value: 1uF; TaMax_C: 125°C; SizeZ_mm: 2.54; SizeX_mm: 4.5; SizeY_mm: 3.2; Value2: 100V; SizeArea_mm2: 14.4; Cap_F: 1µF; IRMS_A: 3.17165A; AEC Category: Q200
D14-D20 = CMP-0078478-2: LED, Green, SMD; Manufacturer: Lite-On; Value2: 2V; Vr_V: 5V; Ir_A: 10µA; Value1: 0.075W; Tjmax_C: 85°C; Green_Lifecycle: Not Set; Angle: 130; Type: AlInGaP; Power_TotalModule: 75mW; Io_A: 30mA; Green_REACh: Incomplete
D21 D22 = CMP-0076902-2: Diode, Switching, 100 V, 0.3 A, LCC-2D; Manufacturer: STMicroelectronics; Value1: 0.3A; Vf_V: 1.2V; Green_REACh: Incomplete; Value: 100V; RJC_CperW: 60.0; SizeX_mm: 7.57; SizeY_mm: 1.97; SizeZ_mm: 2.2; SizeAreaWB_mm2: 37.9929; TJmax_C: 175°C; Io_A: 300mA; AEC Category: Q101; SizeArea_mm2: 14.9129; Green_Lifecycle: Not Set
J49-J54 J59 = CMP-0075483-1: Header, 100mil, 2x1, Gold, TH; Manufacturer: Samtec; Green_REACh: Passed; CT: False; Green_Lifecycle: Active; CNHeader: True
J56 = CMP-0075484-1: Header, 100mil, 3x1, Gold, TH; Manufacturer: Samtec; Green_REACh: Passed; Green_Lifecycle: Active; CT: False; CNHeader: True
L24-L29 = CMP-0003365-1: Ferrite Bead, 120 ohm @ 100 MHz, 3.5 A, 1206; PartNumber: BLM31PG121SN1L; Manufacturer: MuRata; Value: 120 ohm; Imax_A: 3.5A; DCR_ohm: 0.02; Value1: 0.02 ohm; SizeAreaWB_mm2: 10.92; SizeArea_mm2: 5.12; SizeX_mm: 3.2; SizeY_mm: 1.6; SizeZ_mm: 1.35; ZTyp@100MHz_Ohm: 120
R502 R503 R514 R515 R525-R528 R545 R546 = CMP-0080698-1: RES, 0, 0%, 1 W, AEC-Q200 Grade 0, 2512; Manufacturer: Kamaya; SizeAreaWB_mm2: 43.16; SizeArea_mm2: 20.16; AEC Qualified: Y; AEC Category: Q200; Value: 0; SizeZ_mm: 0.71; SizeY_mm: 3.2; Power_W: 1W; SizeX_mm: 6.3
R504 R516 R529 = CMP-0017563-3: RES, 3.65 k, 1%, 0.25 W, AEC-Q200 Grade 0, 1206; Manufacturer: Panasonic; Power_W: 250mW; TempCo: 100 ppm/C; Value_Code: 3k65; Value: 3.65k; EIA_Code: E96; SizeX_mm: 3.2; SizeY_mm: 1.6; SizeZ_mm: 1.35; Value2: 0.25W; SizeArea_mm2: 5.12; AEC Qualified: Y; VDC_V: 200V; AEC Category: Q200; AEC Grade: 0; SizeAreaWB_mm2: 10.92
R505 R513 R517 R524 R530 R537 = CMP-0079710-1: RES, 49.9, 1%, 0.15 W, 0805; Manufacturer: TT Electronics/IRC; Power_W: 150mW; TempCo: 100 ppm/C; SizeAreaWB_mm2: 6.75; Value_Code: 49R9; Value: 49.9; EIA_Code: E96; SizeX_mm: 2; SizeY_mm: 1.25; SizeZ_mm: 1.45; Value2: 0.15W; SizeArea_mm2: 2.5; AEC Qualified: N; AEC Category: Q200
R506 = CMP-0021042-3: RES, 20.0 k, 1%, 0.125 W, AEC-Q200 Grade 0, 0805; Manufacturer: Vishay-Dale; Power_W: 125mW; TempCo: 100 ppm/C; Value_Code: 20k0; Value: 20.0k; EIA_Code: E96; Res_ohm: 20k; SizeX_mm: 2; SizeY_mm: 1.25; SizeZ_mm: 1.45; Value2: 0.125W; SizeArea_mm2: 2.5; AEC Qualified: Y; VDC_V: 150V; AEC Category: Q200; AEC Grade: 0
R507 R518 R531 = CMP-0021614-3: RES, 20.0 k, 1%, 0.125 W, AEC-Q200 Grade 0, 0805; PartNumber: ERJ-6ENF2002V; Manufacturer: Panasonic; Value: 20.0k; Res_ohm: 20k; Value_Code: 20k0; Power_W: 125mW; Value2: 0.125W; TempCo: 100 ppm/C; SizeArea_mm2: 2.5; SizeX_mm: 2; SizeY_mm: 1.25; SizeZ_mm: 1.45; EIA_Code: E96; AEC Category: Q200; AEC Qualified: Y; AEC Grade: 0; SizeAreaWB_mm2: 6.75
R508 R510 R519 R521 R532 R534 R549 R551 = CMP-0081857-1: RES, 0, 0%,  W, AEC-Q200 Grade 0, 0805; Manufacturer: Rohm; SizeAreaWB_mm2: 6.75; SizeArea_mm2: 2.5; AEC Qualified: Y; AEC Category: Q200; Value: 0; SizeZ_mm: 1.45; SizeY_mm: 1.25; SizeX_mm: 2
R509 R520 R533 = CMP-0020154-2: RES, 51.1 k, 0.1%, 0.125 W, 0805; Manufacturer: Yageo America; Power_W: 125mW; TempCo: 25 ppm/C; Value_Code: 51k1; U/M: EA; Value: 51.1k; EIA_Code: E192; SizeX_mm: 2; SizeY_mm: 1.25; SizeZ_mm: 1.45; Value2: 0.125W; SizeArea_mm2: 2.5; VDC_V: 150V; AEC Category: Q200
R511 R512 R522 R523 R535 R536 = CMP-0019490-2: RES, 11.5 k, 0.1%, 0.125 W, 0805; Manufacturer: Yageo America; Power_W: 125mW; TempCo: 25 ppm/C; Value_Code: 11k5; U/M: EA; Value: 11.5k; EIA_Code: E192; SizeX_mm: 2; SizeY_mm: 1.25; SizeZ_mm: 1.45; Value2: 0.125W; SizeArea_mm2: 2.5; VDC_V: 150V; AEC Category: Q200
R538-R541 = CMP-0021991-4: RES, 100, 1%, 0.1 W, AEC-Q200 Grade 0, 0603; Manufacturer: Vishay-Dale; PartNumber: CRCW0603100RFKEA; VDC_V: 75V; Power_W: 100mW; Value: 100; Value_Code: 100R; Value2: 0.1W; EIA_Code: E96; TempCo: 100 ppm/C; SizeArea_mm2: 1.28; SizeX_mm: 1.6; SizeY_mm: 0.8; SizeZ_mm: 1; AEC Category: Q200; AEC Qualified: Y; AEC Grade: 0
R542-R544 = CMP-0022839-5: RES, 178, 1%, 0.1 W, 0603; Manufacturer: Yageo; SizeZ_mm: 1; Value2: 0.1W; SizeArea_mm2: 1.28; AEC Qualified: N; VDC_V: 75V; AEC Category: Q200; Power_W: 100mW; TempCo: 100 ppm/C; Value_Code: 178R; Value: 178; EIA_Code: E96; SizeX_mm: 1.6; SizeY_mm: 0.8; SizeAreaWB_mm2: 4.68
R547 R552 = CMP-0020126-2: RES, 49.9, 0.1%, 0.125 W, 0805; Manufacturer: Yageo America; Power_W: 125mW; TempCo: 25 ppm/C; Value_Code: 49R9; U/M: EA; Value: 49.9; EIA_Code: E192; SizeX_mm: 2; SizeY_mm: 1.25; SizeZ_mm: 1.45; Value2: 0.125W; SizeArea_mm2: 2.5; VDC_V: 150V; AEC Category: Q200
R548 = CMP-0020387-2: RES, 8.66 k, 0.1%, 0.125 W, 0805; Manufacturer: Yageo America; Power_W: 125mW; TempCo: 25 ppm/C; Value_Code: 8k66; U/M: EA; Value: 8.66k; EIA_Code: E192; SizeX_mm: 2; SizeY_mm: 1.25; SizeZ_mm: 1.45; Value2: 0.125W; SizeArea_mm2: 2.5; VDC_V: 150V; AEC Category: Q200
R550 = CMP-0020035-2: RES, 3.20 k, 0.1%, 0.125 W, 0805; Manufacturer: Yageo America; Power_W: 125mW; TempCo: 25 ppm/C; Value_Code: 3k20; U/M: EA; Value: 3.20k; EIA_Code: E192; Res_ohm: 3.2k; SizeX_mm: 2; SizeY_mm: 1.25; SizeZ_mm: 1.45; Value2: 0.125W; SizeArea_mm2: 2.5; VDC_V: 150V; AEC Category: Q200
TP39-TP41 TP46 TP52-TP54 TP59 TP65-TP67 TP72 TP78 TP79 = CMP-0055137-2: Test Point, Miniature, Red, TH; Manufacturer: Keystone Electronics; CNHeader: FALSE; Green_Lifecycle: Active; Green_REACh: Passed; ContactFinish: Silver; CT: TRUE
TP42 TP44 TP45 TP47 TP55 TP57 TP58 TP60 TP68 TP70 TP71 TP73 = CMP-0055139-2: Test Point, Miniature, White, TH; Manufacturer: Keystone Electronics; ContactFinish: Silver; Green_Lifecycle: Active; Green_REACh: Passed; CNHeader: FALSE; CT: TRUE
TP43 TP48-TP51 TP56 TP61-TP64 TP69 TP74-TP77 TP80-TP82 = CMP-0055152-2: Test Point, Miniature, SMT; Manufacturer: Keystone Electronics; CNHeader: FALSE; Green_Lifecycle: Active; Green_REACh: Passed; CT: TRUE
U31-U33 = CMP-0860535-1: 1.5 -7V Input, 3 Amp, Ultra Low Dropout Regulator, HKR0016A (CFP-16); Alternate Manufacturer: Texas Instruments; SizeArea_mm2: 283.09892; SizeX_mm: 25.142; SizeAreaWB_mm2: 359.90292; SizeZ_mm: 2.33; SizeY_mm: 11.26; AEC Category: Q200; CompType: IC
U34 U36 = CMP-0051942-2: Triple Inverter Buffer/Driver with Open-Drain Output, DCU0008A (VSSOP-8); Manufacturer: Texas Instruments; Schmitt Trigger: No; Technology Family: LVC; Input Type: CMOS/TTL; VCC(Max)(V): 5.5; Rating: Catalog; Output Drive (IOL/IOH)(Max)(mA): 32/-32; Voltage(Nom)(V): 1.8,2.5,3.3,5; tpd @ Nom Voltage(Max)(ns): 7.8,4.5,4,3.5; Logic: Inverting; ICC @ Nom Voltage(Max)(mA): 0.01; F @ Nom Voltage(Max)(Mhz): 150; VCC(Min)(V): 1.65; Output Type: CMOS; Bits(#): 3; AEC Category: Q200; AEC Qualified: N; CompType: IC; SizeAreaWB_mm2: 12.6; SizeArea_mm2: 6.4; SizeX_mm: 3.2; SizeY_mm: 2.0; SizeZ_mm: 0.9
U35 = CMP-0067526-3: Wide Vin Low-Dropout Voltage Regulator, HKU0010A (CFP-10); Manufacturer: Texas Instruments; SizeZ_mm: 2.59; CompType: IC; AEC Category: Q200; AEC Qualified: N; Rating: Space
